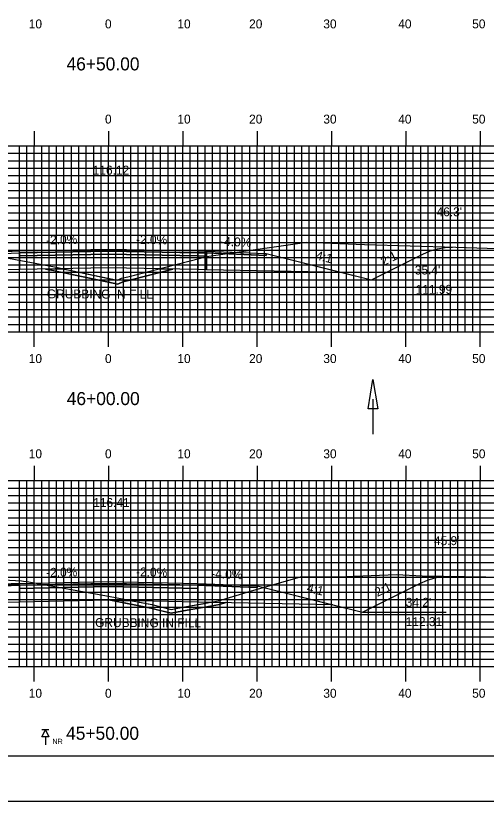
# Model space of a CAD drawing. Extents: x 1754314 to 1754654, y 442591 to 442811.
# Drawn here: x 1754467.5 to 1754530.8, y 442590.5 to 442696.2 of the extents above; entities that cross this region are included whole.
import ezdxf

# ---------------------------------------------------------------- set-up
doc = ezdxf.new("R2010")
doc.units = 0
for name, color, linetype in [('ANNOTATION', 7, 'Continuous'), ('BORDER', 7, 'Continuous'), ('BORING - NO REFUSAL', 7, 'Continuous'), ('D_Drainage_Ditch_Line', 7, 'Continuous'), ('D_Roadway_Centerline', 7, 'Continuous'), ('D_Roadway_Centerline_Text', 7, 'Continuous'), ('D_Roadway_Edge_Shoulder', 7, 'Continuous'), ('D_Roadway_Edge_TW', 7, 'Continuous'), ('D_Roadway_Pavement', 7, 'Continuous'), ('D_Roadway_SlopeLines', 7, 'Continuous'), ('D_Roadway_SubGrade', 7, 'Continuous'), ('D_Text_Standard', 7, 'Continuous'), ('GRUBBING IN FILL', 7, 'Continuous'), ('H_V ANNOTATION', 7, 'Continuous'), ('MAJOR', 7, 'Continuous'), ('MINOR', 7, 'Continuous'), ('PDRAIN', 7, 'Continuous'), ('PLOT BOUNDARY', 7, 'Continuous'), ('S_Roadway_Centerline', 7, 'Continuous')]:
    doc.layers.add(name, color=color, linetype=linetype)

msp = doc.modelspace()

# ---------------------------------------------------------------- linework, layer by layer
at = {"layer": 'BORDER'}
msp.add_lwpolyline([(1754330.4, 442596.67), (1754650.4, 442596.67), (1754650.4, 442806.67), (1754330.4, 442806.67)], close=True, dxfattribs=at)
at = {"layer": 'BORING - NO REFUSAL'}
for p, q in [((1754471.98, 442600.17), (1754471.02, 442600.17)), ((1754471.5, 442599.21), (1754471.5, 442598.15))]:
    msp.add_line(p, q, dxfattribs=at)
msp.add_lwpolyline([(1754471.5, 442600.17), (1754471.98, 442599.21), (1754471.02, 442599.21)], close=True, dxfattribs=at)
at = {"layer": 'D_Drainage_Ditch_Line'}
msp.add_line((1754515.58, 442644.63), (1754515.58, 442639.93), dxfattribs=at)
msp.add_lwpolyline([(1754516.23, 442643.32), (1754514.92, 442643.32), (1754515.58, 442647.25)], close=True, dxfattribs=at)
at = {"layer": 'D_Roadway_Centerline'}
for points in [[(1754449.66, 442661.64), (1754449.83, 442661.68), (1754460, 442664.22), (1754468, 442664.54), (1754480, 442664.78), (1754492, 442664.54), (1754493.2, 442664.52), (1754501.2, 442664.2), (1754511.38, 442661.65), (1754515.38, 442660.65), (1754522.28, 442664.11), (1754523.28, 442664.54), (1754524.28, 442664.84), (1754525.28, 442665.01), (1754526.28, 442665.04)], [(1754454.33, 442618.1), (1754460, 442619.52), (1754468, 442619.84), (1754480, 442620.08), (1754492, 442619.84), (1754500, 442619.52), (1754510.18, 442616.97), (1754514.18, 442615.97), (1754521.9, 442619.83), (1754522.9, 442620.27), (1754523.9, 442620.58), (1754524.9, 442620.75), (1754525.9, 442620.8)]]:
    msp.add_lwpolyline(points, dxfattribs=at)
at = {"layer": 'D_Roadway_Edge_Shoulder'}
for points in [[(1754468, 442664.54), (1754460, 442664.22), (1754460, 442663.97), (1754468, 442664.29)], [(1754493.2, 442664.52), (1754501.2, 442664.2), (1754501.2, 442663.95), (1754493.2, 442664.27)], [(1754468, 442619.84), (1754460, 442619.52), (1754460, 442619.27), (1754468, 442619.59)], [(1754492, 442619.84), (1754500, 442619.52), (1754500, 442619.27), (1754492, 442619.59)]]:
    msp.add_lwpolyline(points, close=True, dxfattribs=at)
at = {"layer": 'D_Roadway_Edge_TW'}
for points in [[(1754468, 442664.29), (1754468, 442664.54), (1754480, 442664.78), (1754492, 442664.54), (1754492, 442664.29), (1754480, 442664.53)], [(1754492, 442664.54), (1754493.2, 442664.52), (1754493.2, 442664.27), (1754492, 442664.29)], [(1754468, 442619.59), (1754468, 442619.84), (1754480, 442620.08), (1754492, 442619.84), (1754492, 442619.59), (1754480, 442619.83)], [(1754492, 442619.84), (1754492, 442619.84), (1754492, 442619.59), (1754492, 442619.59)]]:
    msp.add_lwpolyline(points, close=True, dxfattribs=at)
at = {"layer": 'D_Roadway_Pavement'}
for points in [[(1754468, 442663.88), (1754468, 442664.29), (1754480, 442664.53), (1754492, 442664.29), (1754492, 442663.88), (1754480, 442664.12)], [(1754492, 442664.29), (1754493.2, 442664.27), (1754493.2, 442663.85), (1754492, 442663.88)], [(1754468, 442619.17), (1754468, 442619.59), (1754480, 442619.83), (1754492, 442619.59), (1754492, 442619.17), (1754480, 442619.41)], [(1754492, 442619.59), (1754492, 442619.59), (1754492, 442619.17), (1754492, 442619.17)]]:
    msp.add_lwpolyline(points, close=True, dxfattribs=at)
for points in [[(1754493.2, 442664.27), (1754493.2, 442663.85)], [(1754493.2, 442664.27), (1754493.2, 442663.85)], [(1754493.2, 442664.27), (1754493.2, 442663.85)], [(1754492, 442619.59), (1754492, 442619.17)], [(1754492, 442619.59), (1754492, 442619.17)], [(1754492, 442619.59), (1754492, 442619.17)]]:
    msp.add_lwpolyline(points, dxfattribs=at)
at = {"layer": 'D_Roadway_SlopeLines'}
for points in [[(1754515.38, 442660.65), (1754522.28, 442664.11), (1754523.28, 442664.54), (1754524.28, 442664.84), (1754525.28, 442665.01), (1754526.28, 442665.04)], [(1754501.2, 442664.2), (1754515.38, 442660.65)], [(1754514.18, 442615.97), (1754521.9, 442619.83), (1754522.9, 442620.27), (1754523.9, 442620.58), (1754524.9, 442620.75), (1754525.9, 442620.8)], [(1754500, 442619.52), (1754514.18, 442615.97)]]:
    msp.add_lwpolyline(points, dxfattribs=at)
at = {"layer": 'D_Roadway_SubGrade'}
for points in [[(1754460, 442663.97), (1754468, 442664.29), (1754468, 442663.88), (1754468, 442662.04), (1754449.83, 442661.68), (1754460, 442664.22)], [(1754468, 442662.04), (1754468, 442663.88), (1754480, 442664.12), (1754492, 442663.88), (1754492, 442662.04), (1754480, 442662.28)], [(1754492, 442663.88), (1754493.2, 442663.85), (1754493.2, 442662.02), (1754492, 442662.04)], [(1754493.2, 442663.85), (1754493.2, 442664.27), (1754501.2, 442663.95), (1754501.2, 442664.2), (1754511.38, 442661.65), (1754493.2, 442662.02)], [(1754460, 442619.27), (1754468, 442619.59), (1754468, 442619.17), (1754468, 442617.34), (1754460, 442617.18), (1754460, 442619.52)], [(1754468, 442617.34), (1754468, 442619.17), (1754480, 442619.41), (1754492, 442619.17), (1754492, 442617.34), (1754480, 442617.58)], [(1754492, 442619.17), (1754492, 442619.59), (1754500, 442619.27), (1754500, 442619.52), (1754510.18, 442616.97), (1754492, 442617.34)], [(1754492, 442619.17), (1754492, 442619.17), (1754492, 442617.34), (1754492, 442617.34)]]:
    msp.add_lwpolyline(points, close=True, dxfattribs=at)
at = {"layer": 'GRUBBING IN FILL'}
for points in [[(1754471.5, 442662.11), (1754473.81, 442662.16), (1754474.97, 442661.92), (1754478.09, 442661.26), (1754480, 442660.86), (1754480, 442660.35), (1754478.07, 442660.75), (1754474.86, 442661.43)], [(1754471.5, 442662.11), (1754473.81, 442662.16), (1754474.97, 442661.92), (1754478.09, 442661.26), (1754480, 442660.86), (1754480, 442660.35), (1754478.07, 442660.75), (1754474.86, 442661.43)], [(1754480, 442660.86), (1754481.2, 442660.6), (1754481.47, 442660.74), (1754481.74, 442660.87), (1754482.58, 442661.05), (1754486.8, 442662.15), (1754488.66, 442662.11), (1754485.68, 442661.34), (1754482.7, 442660.57), (1754481.91, 442660.39), (1754481.27, 442660.08), (1754480, 442660.35)], [(1754480, 442660.86), (1754481.2, 442660.6), (1754481.47, 442660.74), (1754481.74, 442660.87), (1754482.58, 442661.05), (1754486.8, 442662.15), (1754488.66, 442662.11), (1754485.68, 442661.34), (1754482.7, 442660.57), (1754481.91, 442660.39), (1754481.27, 442660.08), (1754480, 442660.35)], [(1754480.27, 442617.57), (1754483.17, 442617.51), (1754485.82, 442617), (1754488.44, 442616.35), (1754489.46, 442616.54), (1754490.49, 442616.74), (1754492.65, 442617.11), (1754493.74, 442617.3), (1754495.78, 442617.26), (1754494.92, 442617), (1754492.75, 442616.62), (1754490.58, 442616.25), (1754488.42, 442615.84), (1754487.06, 442616.17), (1754485.71, 442616.51), (1754482.99, 442617.04)], [(1754480.27, 442617.57), (1754483.17, 442617.51), (1754485.82, 442617), (1754488.44, 442616.35), (1754489.46, 442616.54), (1754490.49, 442616.74), (1754492.65, 442617.11), (1754493.74, 442617.3), (1754495.78, 442617.26), (1754494.92, 442617), (1754492.75, 442616.62), (1754490.58, 442616.25), (1754488.42, 442615.84), (1754487.06, 442616.17), (1754485.71, 442616.51), (1754482.99, 442617.04)]]:
    msp.add_lwpolyline(points, close=True, dxfattribs=at)
for points in [[(1754471.5, 442662.11), (1754472.61, 442661.9), (1754474.86, 442661.43), (1754481.27, 442660.08), (1754481.91, 442660.39), (1754482.7, 442660.57), (1754488.66, 442662.11)], [(1754471.5, 442662.11), (1754472.61, 442661.9), (1754474.86, 442661.43), (1754481.27, 442660.08), (1754481.91, 442660.39), (1754482.7, 442660.57), (1754488.66, 442662.11)], [(1754480.27, 442617.57), (1754485.71, 442616.51), (1754488.42, 442615.84), (1754490.58, 442616.25), (1754494.92, 442617), (1754495.78, 442617.26)], [(1754480.27, 442617.57), (1754485.71, 442616.51), (1754488.42, 442615.84), (1754490.58, 442616.25), (1754494.92, 442617), (1754495.78, 442617.26)]]:
    msp.add_lwpolyline(points, dxfattribs=at)
at = {"layer": 'MAJOR'}
for p, q in [((1754470, 442680.67), (1754470, 442678.67)), ((1754480, 442680.67), (1754480, 442678.67)), ((1754490, 442680.67), (1754490, 442678.67)), ((1754500, 442680.67), (1754500, 442678.67)), ((1754510, 442680.67), (1754510, 442678.67)), ((1754520, 442680.67), (1754520, 442678.67)), ((1754530, 442680.67), (1754530, 442678.67)), ((1754340, 442678.67), (1754620, 442678.67)), ((1754340, 442678.67), (1754620, 442678.67)), ((1754470, 442653.67), (1754470, 442678.67)), ((1754480, 442653.67), (1754480, 442678.67)), ((1754490, 442653.67), (1754490, 442678.67)), ((1754500, 442653.67), (1754500, 442678.67)), ((1754510, 442653.67), (1754510, 442678.67)), ((1754520, 442653.67), (1754520, 442678.67)), ((1754530, 442653.67), (1754530, 442678.67)), ((1754340, 442668.67), (1754620, 442668.67)), ((1754340, 442663.67), (1754620, 442663.67)), ((1754340, 442658.67), (1754620, 442658.67)), ((1754340, 442653.67), (1754620, 442653.67)), ((1754340, 442653.67), (1754620, 442653.67)), ((1754470, 442651.66), (1754470, 442653.67)), ((1754480, 442651.66), (1754480, 442653.67)), ((1754480, 442651.66), (1754480, 442653.67)), ((1754490, 442651.66), (1754490, 442653.67)), ((1754500, 442651.66), (1754500, 442653.67)), ((1754510, 442651.66), (1754510, 442653.67)), ((1754520, 442651.66), (1754520, 442653.67)), ((1754530, 442651.66), (1754530, 442653.67)), ((1754470, 442635.67), (1754470, 442633.67)), ((1754480, 442635.67), (1754480, 442633.67)), ((1754490, 442635.67), (1754490, 442633.67)), ((1754500, 442635.67), (1754500, 442633.67)), ((1754510, 442635.67), (1754510, 442633.67)), ((1754520, 442635.67), (1754520, 442633.67)), ((1754530, 442635.67), (1754530, 442633.67)), ((1754340, 442633.67), (1754620, 442633.67)), ((1754340, 442633.67), (1754620, 442633.67)), ((1754470, 442608.67), (1754470, 442633.67)), ((1754480, 442608.67), (1754480, 442633.67)), ((1754490, 442608.67), (1754490, 442633.67)), ((1754500, 442608.67), (1754500, 442633.67)), ((1754510, 442608.67), (1754510, 442633.67)), ((1754520, 442608.67), (1754520, 442633.67)), ((1754530, 442608.67), (1754530, 442633.67)), ((1754340, 442628.67), (1754620, 442628.67)), ((1754340, 442623.67), (1754620, 442623.67)), ((1754340, 442618.67), (1754620, 442618.67)), ((1754340, 442613.67), (1754620, 442613.67)), ((1754340, 442608.67), (1754620, 442608.67)), ((1754340, 442608.67), (1754620, 442608.67)), ((1754470, 442606.66), (1754470, 442608.67)), ((1754480, 442606.66), (1754480, 442608.67)), ((1754480, 442606.66), (1754480, 442608.67)), ((1754480, 442606.66), (1754480, 442608.67)), ((1754490, 442606.66), (1754490, 442608.67)), ((1754500, 442606.66), (1754500, 442608.67)), ((1754510, 442606.66), (1754510, 442608.67)), ((1754520, 442606.66), (1754520, 442608.67)), ((1754530, 442606.66), (1754530, 442608.67))]:
    msp.add_line(p, q, dxfattribs=at)
at = {"layer": 'MINOR'}
for p, q in [((1754468, 442653.67), (1754468, 442678.67)), ((1754469, 442653.67), (1754469, 442678.67)), ((1754471, 442653.67), (1754471, 442678.67)), ((1754472, 442653.67), (1754472, 442678.67)), ((1754473, 442653.67), (1754473, 442678.67)), ((1754474, 442653.67), (1754474, 442678.67)), ((1754475, 442653.67), (1754475, 442678.67)), ((1754476, 442653.67), (1754476, 442678.67)), ((1754477, 442653.67), (1754477, 442678.67)), ((1754478, 442653.67), (1754478, 442678.67)), ((1754479, 442653.67), (1754479, 442678.67)), ((1754481, 442653.67), (1754481, 442678.67)), ((1754482, 442653.67), (1754482, 442678.67)), ((1754483, 442653.67), (1754483, 442678.67)), ((1754484, 442653.67), (1754484, 442678.67)), ((1754485, 442653.67), (1754485, 442678.67)), ((1754486, 442653.67), (1754486, 442678.67)), ((1754487, 442653.67), (1754487, 442678.67)), ((1754488, 442653.67), (1754488, 442678.67)), ((1754489, 442653.67), (1754489, 442678.67)), ((1754491, 442653.67), (1754491, 442678.67)), ((1754492, 442653.67), (1754492, 442678.67)), ((1754493, 442653.67), (1754493, 442678.67)), ((1754494, 442653.67), (1754494, 442678.67)), ((1754495, 442653.67), (1754495, 442678.67)), ((1754496, 442653.67), (1754496, 442678.67)), ((1754497, 442653.67), (1754497, 442678.67)), ((1754498, 442653.67), (1754498, 442678.67)), ((1754499, 442653.67), (1754499, 442678.67)), ((1754501, 442653.67), (1754501, 442678.67)), ((1754502, 442653.67), (1754502, 442678.67)), ((1754503, 442653.67), (1754503, 442678.67)), ((1754504, 442653.67), (1754504, 442678.67)), ((1754505, 442653.67), (1754505, 442678.67)), ((1754506, 442653.67), (1754506, 442678.67)), ((1754507, 442653.67), (1754507, 442678.67)), ((1754508, 442653.67), (1754508, 442678.67)), ((1754509, 442653.67), (1754509, 442678.67)), ((1754511, 442653.67), (1754511, 442678.67)), ((1754512, 442653.67), (1754512, 442678.67)), ((1754513, 442653.67), (1754513, 442678.67)), ((1754514, 442653.67), (1754514, 442678.67)), ((1754515, 442653.67), (1754515, 442678.67)), ((1754516, 442653.67), (1754516, 442678.67)), ((1754517, 442653.67), (1754517, 442678.67)), ((1754518, 442653.67), (1754518, 442678.67)), ((1754519, 442653.67), (1754519, 442678.67)), ((1754521, 442653.67), (1754521, 442678.67)), ((1754522, 442653.67), (1754522, 442678.67)), ((1754523, 442653.67), (1754523, 442678.67)), ((1754524, 442653.67), (1754524, 442678.67)), ((1754525, 442653.67), (1754525, 442678.67)), ((1754526, 442653.67), (1754526, 442678.67)), ((1754527, 442653.67), (1754527, 442678.67)), ((1754528, 442653.67), (1754528, 442678.67)), ((1754529, 442653.67), (1754529, 442678.67)), ((1754340, 442677.67), (1754620, 442677.67)), ((1754340, 442676.67), (1754620, 442676.67)), ((1754340, 442675.67), (1754620, 442675.67)), ((1754340, 442674.67), (1754620, 442674.67)), ((1754340, 442673.67), (1754620, 442673.67)), ((1754340, 442672.67), (1754620, 442672.67)), ((1754340, 442671.67), (1754620, 442671.67)), ((1754340, 442670.67), (1754620, 442670.67)), ((1754340, 442669.67), (1754620, 442669.67)), ((1754340, 442667.67), (1754620, 442667.67)), ((1754340, 442666.67), (1754620, 442666.67)), ((1754340, 442665.67), (1754620, 442665.67)), ((1754340, 442664.67), (1754620, 442664.67)), ((1754340, 442662.67), (1754620, 442662.67)), ((1754340, 442661.67), (1754620, 442661.67)), ((1754340, 442660.67), (1754620, 442660.67)), ((1754340, 442659.67), (1754620, 442659.67)), ((1754340, 442657.67), (1754620, 442657.67)), ((1754340, 442656.67), (1754620, 442656.67)), ((1754340, 442655.67), (1754620, 442655.67)), ((1754340, 442654.67), (1754620, 442654.67)), ((1754468, 442608.67), (1754468, 442633.67)), ((1754469, 442608.67), (1754469, 442633.67)), ((1754471, 442608.67), (1754471, 442633.67)), ((1754472, 442608.67), (1754472, 442633.67)), ((1754473, 442608.67), (1754473, 442633.67)), ((1754474, 442608.67), (1754474, 442633.67)), ((1754475, 442608.67), (1754475, 442633.67)), ((1754476, 442608.67), (1754476, 442633.67)), ((1754477, 442608.67), (1754477, 442633.67)), ((1754478, 442608.67), (1754478, 442633.67)), ((1754479, 442608.67), (1754479, 442633.67)), ((1754481, 442608.67), (1754481, 442633.67)), ((1754482, 442608.67), (1754482, 442633.67)), ((1754483, 442608.67), (1754483, 442633.67)), ((1754484, 442608.67), (1754484, 442633.67)), ((1754485, 442608.67), (1754485, 442633.67)), ((1754486, 442608.67), (1754486, 442633.67)), ((1754487, 442608.67), (1754487, 442633.67)), ((1754488, 442608.67), (1754488, 442633.67)), ((1754489, 442608.67), (1754489, 442633.67)), ((1754491, 442608.67), (1754491, 442633.67)), ((1754492, 442608.67), (1754492, 442633.67)), ((1754493, 442608.67), (1754493, 442633.67)), ((1754494, 442608.67), (1754494, 442633.67)), ((1754495, 442608.67), (1754495, 442633.67)), ((1754496, 442608.67), (1754496, 442633.67)), ((1754497, 442608.67), (1754497, 442633.67)), ((1754498, 442608.67), (1754498, 442633.67)), ((1754499, 442608.67), (1754499, 442633.67)), ((1754501, 442608.67), (1754501, 442633.67)), ((1754502, 442608.67), (1754502, 442633.67)), ((1754503, 442608.67), (1754503, 442633.67)), ((1754504, 442608.67), (1754504, 442633.67)), ((1754505, 442608.67), (1754505, 442633.67)), ((1754506, 442608.67), (1754506, 442633.67)), ((1754507, 442608.67), (1754507, 442633.67)), ((1754508, 442608.67), (1754508, 442633.67)), ((1754509, 442608.67), (1754509, 442633.67)), ((1754511, 442608.67), (1754511, 442633.67)), ((1754512, 442608.67), (1754512, 442633.67)), ((1754513, 442608.67), (1754513, 442633.67)), ((1754514, 442608.67), (1754514, 442633.67)), ((1754515, 442608.67), (1754515, 442633.67)), ((1754516, 442608.67), (1754516, 442633.67)), ((1754517, 442608.67), (1754517, 442633.67)), ((1754518, 442608.67), (1754518, 442633.67)), ((1754519, 442608.67), (1754519, 442633.67)), ((1754521, 442608.67), (1754521, 442633.67)), ((1754522, 442608.67), (1754522, 442633.67)), ((1754523, 442608.67), (1754523, 442633.67)), ((1754524, 442608.67), (1754524, 442633.67)), ((1754525, 442608.67), (1754525, 442633.67)), ((1754526, 442608.67), (1754526, 442633.67)), ((1754527, 442608.67), (1754527, 442633.67)), ((1754528, 442608.67), (1754528, 442633.67)), ((1754529, 442608.67), (1754529, 442633.67)), ((1754340, 442632.67), (1754620, 442632.67)), ((1754340, 442631.67), (1754620, 442631.67)), ((1754340, 442630.67), (1754620, 442630.67)), ((1754340, 442629.67), (1754620, 442629.67)), ((1754340, 442627.67), (1754620, 442627.67)), ((1754340, 442626.67), (1754620, 442626.67)), ((1754340, 442625.67), (1754620, 442625.67)), ((1754340, 442624.67), (1754620, 442624.67)), ((1754340, 442622.67), (1754620, 442622.67)), ((1754340, 442621.67), (1754620, 442621.67)), ((1754340, 442620.67), (1754620, 442620.67)), ((1754340, 442619.67), (1754620, 442619.67)), ((1754340, 442617.67), (1754620, 442617.67)), ((1754340, 442616.67), (1754620, 442616.67)), ((1754340, 442615.67), (1754620, 442615.67)), ((1754340, 442614.67), (1754620, 442614.67)), ((1754340, 442612.67), (1754620, 442612.67)), ((1754340, 442611.67), (1754620, 442611.67)), ((1754340, 442610.67), (1754620, 442610.67)), ((1754340, 442609.67), (1754620, 442609.67))]:
    msp.add_line(p, q, dxfattribs=at)
at = {"layer": 'PDRAIN'}
for p, q in [((1754515.38, 442660.65), (1754526.65, 442660.65)), ((1754514.18, 442615.97), (1754525.45, 442615.97))]:
    msp.add_line(p, q, dxfattribs=at)
at = {"layer": 'PLOT BOUNDARY'}
msp.add_lwpolyline([(1754314.22, 442590.55), (1754654.22, 442590.55), (1754654.22, 442810.55), (1754314.22, 442810.55)], close=True, dxfattribs=at)
at = {"layer": 'S_Roadway_Centerline'}
for points in [[(1754460.84, 442664.64), (1754468.2, 442663.25), (1754472.71, 442662.39), (1754474.97, 442661.92), (1754481.2, 442660.6), (1754481.74, 442660.87), (1754482.58, 442661.05), (1754492.38, 442663.59), (1754493.01, 442663.74), (1754493.49, 442663.82), (1754506.67, 442665.71), (1754514.44, 442665.43), (1754526.71, 442665.03), (1754533.76, 442664.81)], [(1754460.14, 442620.63), (1754468.27, 442620.18), (1754468.56, 442620.16), (1754468.99, 442620.1), (1754479.99, 442618.14), (1754485.82, 442617), (1754488.44, 442616.35), (1754490.49, 442616.74), (1754494.8, 442617.49), (1754499.12, 442618.8), (1754505.84, 442620.73), (1754511.92, 442620.78), (1754518.74, 442621.06), (1754522.19, 442620.87), (1754530.77, 442620.71), (1754542.29, 442620.44)]]:
    msp.add_lwpolyline(points, dxfattribs=at)

# ---------------------------------------------------------------- texts
at = {"layer": 'ANNOTATION'}
for s, rotation, p in [('-2.0%', 1.1458, (1754471.61, 442665.41)), ('-2.0%', 358.8542, (1754483.69, 442665.51)), ('-4.0%', 357.7094, (1754495, 442665.25)), ('4:1', 345.9638, (1754507.8, 442663.41)), ('2:1', 26.5651, (1754516.98, 442662.49)), ('-2.0%', 1.1458, (1754471.61, 442620.71)), ('-2.0%', 358.8542, (1754483.69, 442620.8)), ('-4.0%', 357.7094, (1754493.8, 442620.57)), ('4:1', 345.9638, (1754506.6, 442618.73)), ('2:1', 26.5651, (1754516.18, 442618.01))]:
    msp.add_text(s, height=1.2, rotation=rotation, dxfattribs=at).set_placement(p)
for s, p in [("35.4'", (1754521.21, 442661.38)), ('111.99', (1754521.32, 442658.78)), ("34.2'", (1754519.99, 442616.7)), ('112.31', (1754519.98, 442614.1))]:
    msp.add_text(s, height=1.2, dxfattribs=at).set_placement(p)
at = {"layer": 'BORING - NO REFUSAL'}
msp.add_text('NR', height=0.7, dxfattribs=at).set_placement((1754472.44, 442598.25))
at = {"layer": 'D_Roadway_Centerline'}
for s, p in [('C', (1754480, 442664.78)), ('L', (1754480, 442664.78)), ('C', (1754480, 442620.08)), ('L', (1754480, 442620.07))]:
    msp.add_text(s, height=0.0146, dxfattribs=at).set_placement(p)
at = {"layer": 'D_Roadway_Centerline_Text'}
for s, p in [('116.12', (1754477.87, 442674.81)), ('116.41', (1754477.93, 442630.11))]:
    msp.add_text(s, height=1.2, dxfattribs=at).set_placement(p)
at = {"layer": 'D_Text_Standard'}
for s, p in [("46.3'", (1754524.14, 442669.21)), ("45.9'", (1754523.79, 442624.99))]:
    msp.add_text(s, height=1.2, dxfattribs=at).set_placement(p)
at = {"layer": 'GRUBBING IN FILL'}
for p in [(1754471.7, 442658.17), (1754478.19, 442613.98)]:
    msp.add_text('GRUBBING IN FILL', height=1.2, rotation=359.8142, dxfattribs=at).set_placement(p)
at = {"layer": 'H_V ANNOTATION'}
for s, height, p in [('10', 1.2, (1754469.26, 442694.47)), ('0', 1.2, (1754479.52, 442694.47)), ('10', 1.2, (1754489.26, 442694.47)), ('20', 1.2, (1754498.91, 442694.47)), ('30', 1.2, (1754508.9, 442694.47)), ('40', 1.2, (1754518.98, 442694.47)), ('50', 1.2, (1754528.93, 442694.47)), ('46+50.00', 1.75, (1754474.34, 442688.82)), ('0', 1.2, (1754479.52, 442681.67)), ('10', 1.2, (1754489.26, 442681.67)), ('20', 1.2, (1754498.91, 442681.67)), ('30', 1.2, (1754508.9, 442681.67)), ('40', 1.2, (1754518.98, 442681.67)), ('50', 1.2, (1754528.93, 442681.67)), ('10', 1.2, (1754469.26, 442649.47)), ('0', 1.2, (1754479.52, 442649.47)), ('0', 1.2, (1754479.52, 442649.47)), ('10', 1.2, (1754489.26, 442649.47)), ('20', 1.2, (1754498.91, 442649.47)), ('30', 1.2, (1754508.9, 442649.47)), ('40', 1.2, (1754518.98, 442649.47)), ('50', 1.2, (1754528.93, 442649.47)), ('46+00.00', 1.75, (1754474.37, 442643.82)), ('10', 1.2, (1754469.26, 442636.67)), ('0', 1.2, (1754479.52, 442636.67)), ('10', 1.2, (1754489.26, 442636.67)), ('20', 1.2, (1754498.91, 442636.67)), ('30', 1.2, (1754508.9, 442636.67)), ('40', 1.2, (1754518.98, 442636.67)), ('50', 1.2, (1754528.93, 442636.67)), ('10', 1.2, (1754469.26, 442604.47)), ('0', 1.2, (1754479.52, 442604.47)), ('0', 1.2, (1754479.52, 442604.47)), ('0', 1.2, (1754479.52, 442604.47)), ('10', 1.2, (1754489.26, 442604.47)), ('20', 1.2, (1754498.91, 442604.47)), ('30', 1.2, (1754508.9, 442604.47)), ('40', 1.2, (1754518.98, 442604.47)), ('50', 1.2, (1754528.93, 442604.47)), ('45+50.00', 1.75, (1754474.28, 442598.82))]:
    msp.add_text(s, height=height, dxfattribs=at).set_placement(p)

doc.saveas('drawing.dxf')
